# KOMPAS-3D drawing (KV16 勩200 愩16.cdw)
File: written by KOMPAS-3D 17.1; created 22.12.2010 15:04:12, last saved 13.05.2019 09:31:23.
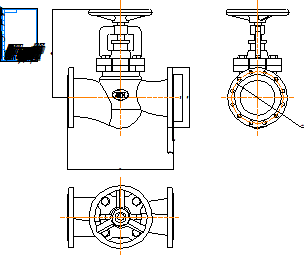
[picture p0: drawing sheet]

Title block, sheet 1: name: KV16 Ду200 Ру16; material: Внимание! Данный продукт является объектом авторского права ООО «Торговый Дом АДЛ». / Запрещается изменение, копирование, распространение / (в том числе путем копирования на другие сайты и ресурсы в Интернете) / или любое иное использование информации и объектов без предварительного / согласия правообладателя (ООО «Торговый Дом АДЛ»).; scale: 1:1; sheets: 1; organisation: ООО "Торговый дом АДЛ"; sheet format: A4; stored path: \\adlc.lan\data\АДЛ_ПКД\3D-модели\ADL production\Вентили ГРАНВЕНТ\KV16\KOMPAS 2D\KV16 Ду200 Ру16.cdw

Views: Спереди 1, Проекционный вид 2, Проекционный вид 3
Dimensions and other numbers on the sheet: 266; 340; 600; 2; 30; 295; 498,5; 1:1; 1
